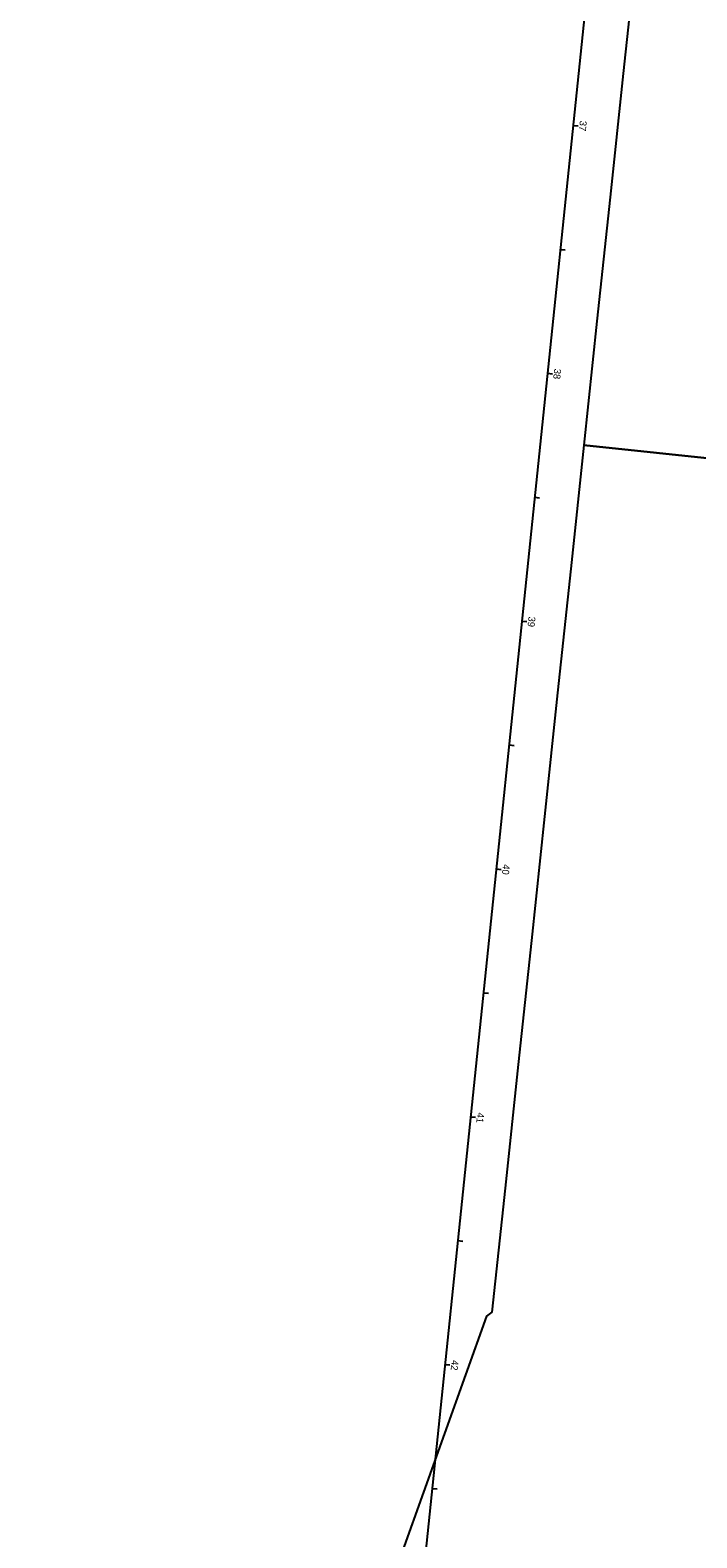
# Model space of a CAD drawing. Extents: x 172043 to 172847, y 249504 to 259737.
# Drawn here: x 172171 to 172439, y 255475 to 256080 of the extents above; entities that cross this region are included whole.
import ezdxf

# ---------------------------------------------------------------- set-up
doc = ezdxf.new("R2010")
doc.units = 0
doc.layers.add('PM_X_Surveyed_Line', color=7, linetype='Continuous')
doc.layers.add('PV_X_Shoulder', color=7, linetype='Continuous')

msp = doc.modelspace()

# ---------------------------------------------------------------- linework, layer by layer
at = {"layer": 'PM_X_Surveyed_Line'}
for p, q in [((172428.67, 256423.35), (172177.28, 253990.91)), ((172409.1, 256234.03), (172171.47, 253934.66)), ((172389.21, 256041.57), (172391.2, 256041.37)), ((172389.21, 256041.57), (172391.2, 256041.37)), ((172384.07, 255991.84), (172386.06, 255991.63)), ((172378.93, 255942.1), (172380.92, 255941.9)), ((172378.93, 255942.1), (172380.92, 255941.9)), ((172373.79, 255892.37), (172375.78, 255892.16)), ((172368.65, 255842.63), (172370.64, 255842.43)), ((172368.65, 255842.63), (172370.64, 255842.43)), ((172363.51, 255792.9), (172365.5, 255792.69)), ((172358.37, 255743.16), (172360.36, 255742.96)), ((172358.37, 255743.16), (172360.36, 255742.96)), ((172353.23, 255693.43), (172355.22, 255693.22)), ((172348.09, 255643.69), (172350.08, 255643.49)), ((172348.09, 255643.69), (172350.08, 255643.49)), ((172342.95, 255593.96), (172344.94, 255593.75)), ((172337.81, 255544.22), (172339.8, 255544.02)), ((172337.81, 255544.22), (172339.8, 255544.02)), ((172332.67, 255494.49), (172334.66, 255494.28))]:
    msp.add_line(p, q, dxfattribs=at)
at = {"layer": 'PV_X_Shoulder'}
for points in [[(172393.52, 255913.31), (172791.29, 255871.19), (172796.56, 255920.91), (172801.83, 255970.63), (172807.09, 256020.35), (172812.36, 256070.07), (172817.62, 256119.8), (172822.89, 256169.52), (172828.15, 256219.24), (172833.42, 256268.96), (172838.68, 256318.68), (172847.18, 256398.96), (172445.03, 256399.72), (172440.91, 256360.81), (172435.64, 256311.09), (172430.38, 256261.36), (172425.11, 256211.64), (172419.85, 256161.92), (172414.58, 256112.2), (172409.32, 256062.48), (172404.05, 256012.75), (172398.78, 255963.03)], [(172320.75, 255469.43), (172697.36, 255334.65), (172714.21, 255381.73), (172731.06, 255428.8), (172754.44, 255523.13), (172759.7, 255572.85), (172764.97, 255622.58), (172770.23, 255672.3), (172775.5, 255722.02), (172780.76, 255771.74), (172786.03, 255821.46), (172791.29, 255871.19), (172393.52, 255913.31), (172388.25, 255863.59), (172382.99, 255813.87), (172377.72, 255764.14), (172372.46, 255714.42), (172367.19, 255664.7), (172361.93, 255614.98), (172356.66, 255565.26), (172354.45, 255563.58), (172337.6, 255516.51)]]:
    msp.add_lwpolyline(points, close=True, dxfattribs=at)

# ---------------------------------------------------------------- texts
at = {"layer": 'PM_X_Surveyed_Line'}
for s, p in [('37', (172391.93, 256043.6)), ('38', (172381.65, 255944.05)), ('39', (172371.36, 255844.57)), ('40', (172361.09, 255745.12)), ('41', (172350.79, 255645.46)), ('42', (172340.52, 255546.12))]:
    msp.add_text(s, height=2.8, rotation=264.09958, dxfattribs=at).set_placement(p)

doc.saveas('drawing.dxf')
